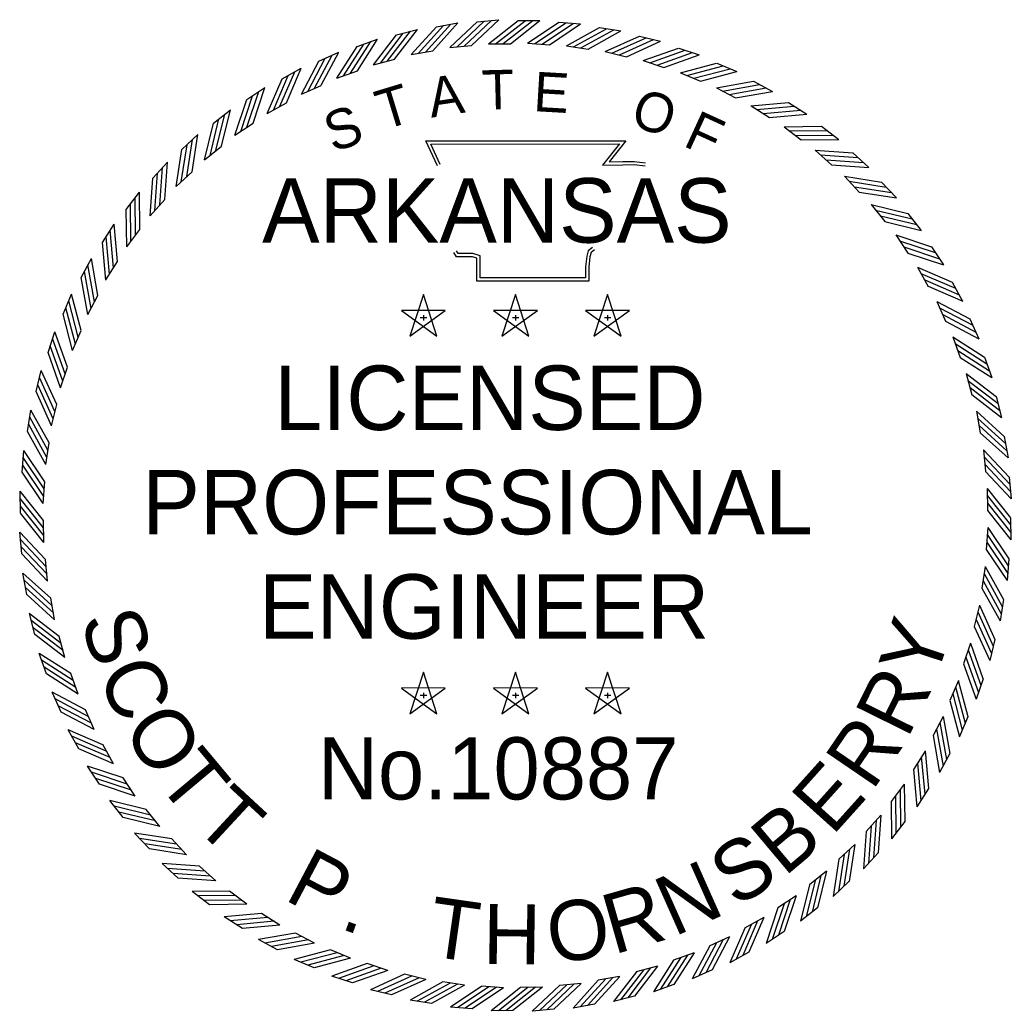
# Model space of a CAD drawing. Extents: x -31696 to 27919, y -8775 to 11152.
# Drawn here: x 3046.5 to 3294.9, y 323.2 to 571.6 of the extents above; entities that cross this region are included whole.
import ezdxf

# ---------------------------------------------------------------- set-up
doc = ezdxf.new("R2010")
doc.units = 0
doc.layers.add('Level 46', color=7, linetype='Continuous')

msp = doc.modelspace()

# ---------------------------------------------------------------- linework, layer by layer
at = {"layer": 'Level 46'}
for p, q in [((3161.08, 571.13), (3166.5, 571.63)), ((3171.39, 571.43), (3176.83, 571.43)), ((3140.85, 567.86), (3146.11, 569.24)), ((3150.9, 569.91), (3156.26, 570.86)), ((3181.58, 571.02), (3187, 570.63)), ((3191.75, 569.7), (3197.12, 568.86)), ((3131.01, 564.98), (3136.14, 566.8)), ((3201.77, 567.55), (3207.06, 566.26)), ((3154.22, 564.68), (3159.65, 565.18)), ((3163.96, 565.64), (3169.41, 565.64)), ((3173.75, 565.8), (3179.19, 565.4)), ((3183.51, 565.14), (3188.9, 564.29)), ((3211.59, 564.57), (3216.75, 562.85)), ((3121.43, 561.3), (3126.4, 563.53)), ((3135.14, 560.37), (3140.42, 561.76)), ((3144.59, 562.92), (3149.96, 563.87)), ((3193.19, 563.68), (3198.49, 562.39)), ((3112.2, 556.85), (3116.96, 559.48)), ((3202.71, 561.42), (3207.89, 559.7)), ((3221.12, 560.8), (3226.13, 558.66)), ((3125.94, 557.05), (3131.08, 558.87)), ((3212.02, 558.39), (3217.03, 556.25)), ((3103.36, 551.64), (3107.89, 554.66)), ((3117.04, 552.98), (3122.01, 555.21)), ((3221.04, 554.6), (3225.86, 552.05)), ((3230.31, 556.24), (3235.12, 553.7)), ((3094.98, 545.72), (3099.24, 549.11)), ((3108.5, 548.19), (3113.27, 550.83)), ((3229.72, 550.08), (3234.32, 547.14)), ((3239.1, 550.95), (3243.68, 548.02)), ((3100.39, 542.71), (3104.93, 545.73)), ((3238, 544.85), (3242.33, 541.54)), ((3247.41, 544.95), (3251.74, 541.64)), ((3087.12, 539.14), (3091.09, 542.86)), ((3092.76, 536.57), (3097.04, 539.96)), ((3245.82, 538.96), (3249.86, 535.3)), ((3255.21, 538.28), (3259.24, 534.63)), ((3079.83, 531.92), (3083.48, 535.96)), ((3085.67, 529.83), (3089.64, 533.56)), ((3253.12, 532.45), (3256.85, 528.47)), ((3262.42, 530.99), (3266.14, 527.02)), ((3073.17, 524.13), (3076.47, 528.45)), ((3079.15, 522.53), (3082.81, 526.58)), ((3259.86, 525.35), (3263.25, 521.08)), ((3269.01, 523.13), (3272.39, 518.87)), ((3067.16, 515.81), (3070.1, 520.39)), ((3073.26, 514.71), (3076.57, 519.05)), ((3265.99, 517.72), (3269.02, 513.18)), ((3274.93, 514.75), (3277.94, 510.23)), ((3061.87, 507.03), (3064.41, 511.84)), ((3068.04, 506.44), (3070.98, 511.03)), ((3271.47, 509.61), (3274.11, 504.84)), ((3280.13, 505.92), (3282.76, 501.15)), ((3057.32, 497.84), (3059.46, 502.84)), ((3063.51, 497.76), (3066.06, 502.58)), ((3147.61, 502.79), (3144.21, 492.34)), ((3151, 492.35), (3147.62, 502.8)), ((3170.69, 502.79), (3167.28, 492.34)), ((3174.08, 492.35), (3170.7, 502.8)), ((3193.77, 502.79), (3190.36, 492.34)), ((3197.16, 492.35), (3193.77, 502.8)), ((3276.26, 501.08), (3278.5, 496.1)), ((3153.1, 498.8), (3142.11, 498.81)), ((3142.12, 498.8), (3151, 492.33)), ((3144.22, 492.35), (3153.11, 498.8)), ((3146.83, 497.04), (3148.46, 497.04)), ((3147.62, 497.63), (3147.62, 496.25)), ((3176.18, 498.8), (3165.19, 498.81)), ((3165.2, 498.8), (3174.08, 492.33)), ((3167.3, 492.35), (3176.19, 498.8)), ((3169.91, 497.04), (3171.54, 497.04)), ((3170.7, 497.63), (3170.7, 496.25)), ((3199.25, 498.8), (3188.27, 498.81)), ((3188.28, 498.8), (3197.16, 492.33)), ((3190.37, 492.35), (3199.27, 498.8)), ((3192.98, 497.04), (3194.62, 497.04)), ((3193.78, 497.63), (3193.78, 496.25)), ((3284.59, 496.68), (3286.82, 491.72)), ((3053.54, 488.3), (3055.26, 493.47)), ((3059.72, 488.74), (3061.86, 493.75)), ((3280.33, 492.18), (3282.15, 487.03)), ((3288.27, 487.11), (3290.08, 481.98)), ((3056.69, 479.43), (3058.41, 484.6)), ((3050.56, 478.49), (3051.85, 483.78)), ((3283.66, 482.97), (3285.04, 477.69)), ((3291.14, 477.26), (3292.53, 472)), ((3054.43, 469.91), (3055.72, 475.2)), ((3048.41, 468.46), (3049.25, 473.84)), ((3286.21, 473.52), (3287.15, 468.15)), ((3293.2, 467.21), (3294.14, 461.86)), ((3052.97, 460.23), (3053.82, 465.61)), ((3047.09, 458.29), (3047.49, 463.72)), ((3287.97, 463.89), (3288.47, 458.46)), ((3052.32, 450.46), (3052.72, 455.9)), ((3294.41, 457.03), (3294.91, 451.61)), ((3046.61, 448.05), (3046.56, 453.49)), ((3288.93, 454.15), (3288.98, 448.7)), ((3052.47, 440.68), (3052.42, 446.13)), ((3294.79, 446.78), (3294.84, 441.34)), ((3046.98, 437.8), (3046.48, 443.22)), ((3289.08, 444.37), (3288.68, 438.93)), ((3053.43, 430.94), (3052.93, 436.37)), ((3294.31, 436.54), (3293.91, 431.11)), ((3048.2, 427.61), (3047.25, 432.97)), ((3288.42, 434.6), (3287.58, 429.21)), ((3055.19, 421.31), (3054.24, 426.68)), ((3286.96, 424.92), (3285.67, 419.62)), ((3292.99, 426.36), (3292.14, 420.99)), ((3050.25, 417.57), (3048.87, 422.83)), ((3057.74, 411.86), (3056.35, 417.13)), ((3284.71, 415.4), (3282.99, 410.22)), ((3290.83, 416.34), (3289.55, 411.05)), ((3053.13, 407.72), (3051.32, 412.85)), ((3061.06, 402.65), (3059.24, 407.79)), ((3147.61, 408.16), (3144.21, 397.72)), ((3151, 397.72), (3147.62, 408.17)), ((3170.69, 408.16), (3167.28, 397.72)), ((3174.08, 397.72), (3170.7, 408.17)), ((3193.77, 408.16), (3190.36, 397.72)), ((3197.16, 397.72), (3193.77, 408.17)), ((3281.68, 406.09), (3279.53, 401.08)), ((3287.86, 406.52), (3286.14, 401.36)), ((3056.81, 398.15), (3054.58, 403.11)), ((3153.1, 404.17), (3142.11, 404.19)), ((3142.12, 404.17), (3151, 397.71)), ((3144.22, 397.72), (3153.11, 404.17)), ((3147.62, 403.01), (3147.62, 401.63)), ((3176.18, 404.17), (3165.19, 404.19)), ((3165.2, 404.17), (3174.08, 397.71)), ((3167.3, 397.72), (3176.19, 404.17)), ((3170.7, 403.01), (3170.7, 401.63)), ((3199.25, 404.17), (3188.27, 404.19)), ((3188.28, 404.17), (3197.16, 397.71)), ((3190.37, 397.72), (3199.27, 404.17)), ((3193.78, 403.01), (3193.78, 401.63)), ((3146.83, 402.42), (3148.46, 402.42)), ((3169.91, 402.42), (3171.54, 402.42)), ((3192.98, 402.42), (3194.62, 402.42)), ((3065.13, 393.75), (3062.9, 398.72)), ((3277.89, 397.07), (3275.33, 392.25)), ((3284.08, 396.99), (3281.94, 391.99)), ((3061.27, 388.91), (3058.63, 393.67)), ((3069.93, 385.22), (3067.29, 389.99)), ((3273.36, 388.39), (3270.42, 383.8)), ((3279.53, 387.8), (3276.98, 382.99)), ((3066.47, 380.07), (3063.45, 384.6)), ((3075.41, 377.11), (3072.38, 381.65)), ((3268.14, 380.11), (3264.83, 375.78)), ((3274.23, 379.01), (3271.3, 374.43)), ((3072.39, 371.7), (3069.01, 375.96)), ((3081.54, 369.48), (3078.15, 373.75)), ((3262.25, 372.3), (3258.59, 368.25)), ((3268.23, 370.7), (3264.93, 366.37)), ((3078.98, 363.84), (3075.25, 367.81)), ((3088.28, 362.38), (3084.55, 366.36)), ((3255.73, 364.99), (3251.75, 361.26)), ((3261.56, 362.91), (3257.92, 358.87)), ((3086.19, 356.55), (3082.15, 360.2)), ((3095.58, 355.87), (3091.54, 359.52)), ((3248.63, 358.25), (3244.36, 354.86)), ((3254.27, 355.69), (3250.31, 351.97)), ((3093.98, 349.88), (3089.66, 353.18)), ((3103.4, 349.98), (3099.06, 353.29)), ((3241, 352.12), (3236.47, 349.1)), ((3246.41, 349.1), (3242.15, 345.72)), ((3102.3, 343.88), (3097.72, 346.81)), ((3111.67, 344.75), (3107.08, 347.69)), ((3232.9, 346.64), (3228.12, 344)), ((3238.04, 343.19), (3233.51, 340.17)), ((3111.08, 338.58), (3106.27, 341.13)), ((3120.35, 340.23), (3115.53, 342.78)), ((3224.36, 341.85), (3219.39, 339.61)), ((3129.38, 336.44), (3124.36, 338.58)), ((3229.2, 337.98), (3224.44, 335.35)), ((3120.27, 334.03), (3115.27, 336.17)), ((3215.46, 337.78), (3210.32, 335.96)), ((3138.68, 333.4), (3133.51, 335.13)), ((3206.25, 334.46), (3200.98, 333.07)), ((3219.96, 333.52), (3215, 331.29)), ((3129.81, 330.26), (3124.65, 331.97)), ((3148.21, 331.15), (3142.91, 332.44)), ((3157.88, 329.69), (3152.5, 330.54)), ((3196.8, 331.91), (3191.43, 330.96)), ((3139.62, 327.28), (3134.34, 328.57)), ((3167.65, 329.03), (3162.21, 329.43)), ((3177.44, 329.18), (3171.98, 329.13)), ((3187.18, 330.14), (3181.75, 329.64)), ((3210.39, 329.84), (3205.26, 328.03)), ((3149.65, 325.12), (3144.28, 325.97)), ((3200.55, 326.97), (3195.28, 325.58)), ((3159.82, 323.8), (3154.39, 324.2)), ((3170.07, 323.33), (3164.62, 323.28)), ((3180.31, 323.7), (3174.9, 323.2)), ((3190.5, 324.91), (3185.14, 323.97))]:
    msp.add_line(p, q, dxfattribs=at)
for points in [[(3157.84, 565.04), (3164.7, 571.48)], [(3159.64, 565.19), (3166.5, 571.63)], [(3163.95, 565.64), (3171.38, 571.43)], [(3165.71, 565.62), (3173.13, 571.41)], [(3167.6, 565.66), (3175.02, 571.45)], [(3169.41, 565.65), (3176.83, 571.44)], [(3140.41, 561.76), (3146.12, 569.25)], [(3144.59, 562.92), (3150.89, 569.91)], [(3146.31, 563.2), (3152.62, 570.19)], [(3148.17, 563.57), (3154.47, 570.56)], [(3149.96, 563.87), (3156.26, 570.86)], [(3154.21, 564.68), (3161.08, 571.12)], [(3155.96, 564.82), (3162.82, 571.27)], [(3173.74, 565.79), (3181.57, 571.02)], [(3175.49, 565.65), (3183.31, 570.88)], [(3177.37, 565.55), (3185.2, 570.78)], [(3179.18, 565.4), (3187.01, 570.63)], [(3183.51, 565.14), (3191.74, 569.7)], [(3185.23, 564.85), (3193.47, 569.41)], [(3187.11, 564.59), (3195.34, 569.16)], [(3131.07, 558.87), (3136.14, 566.8)], [(3135.14, 560.36), (3140.84, 567.85)], [(3136.84, 560.79), (3142.54, 568.28)], [(3138.65, 561.32), (3144.36, 568.8)], [(3188.89, 564.3), (3197.13, 568.86)], [(3193.18, 563.68), (3201.77, 567.55)], [(3194.88, 563.25), (3203.46, 567.12)], [(3196.73, 562.84), (3205.31, 566.71)], [(3125.93, 557.04), (3131, 564.98)], [(3127.59, 557.61), (3132.66, 565.54)], [(3129.36, 558.28), (3134.42, 566.21)], [(3198.48, 562.39), (3207.07, 566.26)], [(3202.71, 561.42), (3211.58, 564.57)], [(3204.36, 560.85), (3213.24, 564)], [(3118.64, 553.67), (3123.03, 562)], [(3120.34, 554.49), (3124.74, 562.81)], [(3122, 555.22), (3126.4, 563.54)], [(3206.17, 560.3), (3215.04, 563.44)], [(3207.88, 559.71), (3216.76, 562.85)], [(3113.27, 550.83), (3116.96, 559.49)], [(3117.03, 552.97), (3121.43, 561.3)], [(3212.01, 558.39), (3221.11, 560.79)], [(3213.62, 557.69), (3222.72, 560.09)], [(3215.37, 556.98), (3224.47, 559.39)], [(3108.5, 548.18), (3112.19, 556.84)], [(3110.04, 549.01), (3113.73, 557.67)], [(3111.67, 549.96), (3115.37, 558.62)], [(3217.03, 556.25), (3226.13, 558.66)], [(3104.92, 545.73), (3107.89, 554.67)], [(3221.04, 554.6), (3230.31, 556.24)], [(3222.58, 553.77), (3231.85, 555.41)], [(3224.27, 552.92), (3233.54, 554.56)], [(3100.39, 542.7), (3103.36, 551.63)], [(3101.86, 543.66), (3104.82, 552.59)], [(3103.41, 544.74), (3106.37, 553.67)], [(3225.86, 552.06), (3235.13, 553.7)], [(3097.03, 539.96), (3099.25, 549.11)], [(3229.71, 550.08), (3239.09, 550.95)], [(3231.18, 549.12), (3240.55, 549.99)], [(3094.14, 537.64), (3096.36, 546.79)], [(3095.6, 538.85), (3097.82, 548)], [(3232.8, 548.13), (3242.17, 549.01)], [(3234.31, 547.14), (3243.69, 548.02)], [(3092.76, 536.57), (3094.98, 545.72)], [(3237.99, 544.85), (3247.4, 544.95)], [(3088.3, 532.34), (3089.76, 541.64)], [(3089.64, 533.56), (3091.09, 542.86)], [(3239.37, 543.78), (3248.79, 543.87)], [(3240.9, 542.66), (3250.31, 542.76)], [(3242.33, 541.55), (3251.74, 541.64)], [(3085.67, 529.83), (3087.12, 539.13)], [(3086.95, 531.01), (3088.41, 540.31)], [(3151.11, 535.02), (3148.21, 541.3), (3198.39, 541.33), (3194.2, 536.06), (3197.61, 536.11), (3200.46, 536.14), (3203.3, 535.83)], [(3151.84, 535.35), (3149.46, 540.5), (3196.74, 540.53), (3192.54, 535.24), (3197.62, 535.31), (3200.42, 535.35), (3203.22, 535.04)], [(3245.81, 538.96), (3255.2, 538.28)], [(3247.1, 537.78), (3256.49, 537.09)], [(3081.57, 525.24), (3082.25, 534.63)], [(3082.8, 526.57), (3083.48, 535.96)], [(3248.53, 536.54), (3257.92, 535.86)], [(3249.86, 535.31), (3259.25, 534.63)], [(3079.15, 522.52), (3079.83, 531.91)], [(3080.34, 523.81), (3081.02, 533.2)], [(3253.11, 532.45), (3262.41, 530.99)], [(3254.3, 531.16), (3263.6, 529.7)], [(3255.62, 529.81), (3264.92, 528.35)], [(3075.45, 517.62), (3075.35, 527.03)], [(3076.56, 519.05), (3076.47, 528.46)], [(3256.85, 528.47), (3266.15, 527.02)], [(3074.34, 516.09), (3074.24, 525.5)], [(3259.85, 525.35), (3269, 523.13)], [(3073.26, 514.71), (3073.16, 524.12)], [(3260.93, 523.97), (3270.08, 521.75)], [(3262.13, 522.51), (3271.28, 520.3)], [(3070.97, 511.03), (3070.1, 520.4)], [(3263.25, 521.08), (3272.4, 518.87)], [(3068.99, 507.9), (3068.12, 517.27)], [(3069.98, 509.51), (3069.1, 518.88)], [(3265.98, 517.72), (3274.92, 514.76)], [(3068.04, 506.43), (3067.16, 515.8)], [(3189.98, 514.61), (3188.93, 513.75), (3188.56, 512.4), (3188.27, 509.7), (3188.27, 506.98), (3161.85, 506.98), (3161.85, 510.87), (3161.85, 512.49), (3160.03, 513.05), (3156.36, 513.05), (3155.89, 513.77)], [(3266.94, 516.26), (3275.88, 513.29)], [(3268.02, 514.71), (3276.96, 511.74)], [(3066.06, 502.57), (3064.41, 511.84)], [(3190.49, 513.99), (3189.63, 513.29), (3189.35, 512.25), (3189.06, 509.65), (3189.06, 506.18), (3161.05, 506.18), (3161.05, 510.87), (3161.05, 511.91), (3159.91, 512.25), (3155.93, 512.25), (3155.22, 513.33)], [(3269.02, 513.19), (3277.95, 510.22)], [(3065.19, 500.98), (3063.55, 510.25)], [(3271.46, 509.61), (3280.12, 505.92)], [(3063.51, 497.75), (3061.87, 507.02)], [(3064.35, 499.29), (3062.7, 508.56)], [(3272.3, 508.07), (3280.96, 504.38)], [(3273.25, 506.44), (3281.91, 502.75)], [(3274.11, 504.85), (3282.77, 501.15)], [(3061.86, 493.75), (3059.46, 502.85)], [(3060.43, 490.33), (3058.02, 499.43)], [(3061.13, 492.09), (3058.73, 501.19)], [(3276.26, 501.08), (3284.58, 496.68)], [(3276.96, 499.48), (3285.28, 495.08)], [(3059.72, 488.73), (3057.32, 497.83)], [(3277.77, 497.77), (3286.1, 493.37)], [(3278.5, 496.11), (3286.83, 491.71)], [(3058.4, 484.6), (3055.26, 493.47)], [(3280.33, 492.18), (3288.26, 487.11)], [(3057.26, 481.08), (3054.11, 489.95)], [(3057.82, 482.88), (3054.67, 491.76)], [(3280.9, 490.52), (3288.83, 485.46)], [(3056.69, 479.42), (3053.54, 488.29)], [(3281.57, 488.76), (3289.5, 483.69)], [(3282.15, 487.04), (3290.09, 481.97)], [(3055.27, 473.44), (3051.4, 482.02)], [(3055.72, 475.2), (3051.85, 483.78)], [(3283.65, 482.97), (3291.14, 477.27)], [(3054.87, 471.6), (3051, 480.18)], [(3284.08, 481.28), (3291.57, 475.57)], [(3054.44, 469.9), (3050.57, 478.48)], [(3284.6, 479.46), (3292.09, 473.75)], [(3285.05, 477.7), (3292.53, 472)], [(3053.52, 463.82), (3048.95, 472.05)], [(3053.82, 465.61), (3049.25, 473.84)], [(3286.2, 473.53), (3293.19, 467.22)], [(3053.26, 461.95), (3048.7, 470.18)], [(3286.49, 471.8), (3293.48, 465.49)], [(3286.86, 469.94), (3293.85, 463.64)], [(3052.98, 460.22), (3048.41, 468.45)], [(3287.16, 468.16), (3294.15, 461.85)], [(3052.71, 455.89), (3047.48, 463.72)], [(3287.96, 463.9), (3294.41, 457.04)], [(3288.11, 462.15), (3294.55, 455.29)], [(3052.47, 452.2), (3047.24, 460.03)], [(3052.56, 454.09), (3047.33, 461.92)], [(3288.32, 460.27), (3294.77, 453.41)], [(3052.32, 450.46), (3047.09, 458.28)], [(3288.47, 458.47), (3294.92, 451.61)], [(3052.41, 446.12), (3046.56, 453.49)], [(3288.92, 454.16), (3294.78, 446.79)], [(3288.92, 452.41), (3294.78, 445.04)], [(3052.41, 444.31), (3046.56, 451.68)], [(3052.47, 442.42), (3046.62, 449.79)], [(3288.98, 450.52), (3294.84, 443.15)], [(3052.47, 440.67), (3046.62, 448.04)], [(3288.98, 448.7), (3294.84, 441.33)], [(3052.93, 436.36), (3046.48, 443.22)], [(3288.93, 442.63), (3294.16, 434.8)], [(3289.08, 444.37), (3294.31, 436.54)], [(3053.08, 434.55), (3046.63, 441.41)], [(3288.83, 440.74), (3294.06, 432.91)], [(3053.29, 432.67), (3046.84, 439.54)], [(3053.43, 430.93), (3046.99, 437.79)], [(3288.68, 438.93), (3293.91, 431.1)], [(3054.24, 426.67), (3047.25, 432.98)], [(3288.13, 432.88), (3292.7, 424.65)], [(3288.42, 434.61), (3292.99, 426.37)], [(3054.54, 424.88), (3047.55, 431.19)], [(3287.88, 431.01), (3292.44, 422.77)], [(3054.91, 423.03), (3047.92, 429.33)], [(3055.2, 421.3), (3048.21, 427.61)], [(3287.58, 429.22), (3292.15, 420.98)], [(3286.96, 424.93), (3290.83, 416.35)], [(3056.35, 417.13), (3048.86, 422.83)], [(3286.53, 423.23), (3290.4, 414.65)], [(3056.8, 415.37), (3049.31, 421.07)], [(3286.12, 421.39), (3289.99, 412.8)], [(3057.32, 413.55), (3049.83, 419.26)], [(3057.75, 411.85), (3050.26, 417.56)], [(3285.68, 419.63), (3289.55, 411.05)], [(3284.71, 415.41), (3287.85, 406.53)], [(3059.24, 407.79), (3051.31, 412.85)], [(3284.14, 413.75), (3287.29, 404.88)], [(3059.83, 406.07), (3051.9, 411.14)], [(3282.99, 410.23), (3286.14, 401.36)], [(3283.58, 411.94), (3286.73, 403.07)], [(3060.5, 404.3), (3052.57, 409.37)], [(3061.07, 402.65), (3053.14, 407.72)], [(3281.67, 406.1), (3284.08, 397)], [(3062.9, 398.72), (3054.57, 403.11)], [(3280.27, 402.74), (3282.67, 393.64)], [(3280.97, 404.5), (3283.37, 395.39)], [(3063.62, 397.06), (3055.3, 401.45)], [(3279.54, 401.08), (3281.94, 391.98)], [(3064.44, 395.35), (3056.11, 399.75)], [(3065.14, 393.75), (3056.82, 398.14)], [(3277.05, 395.54), (3278.69, 386.27)], [(3277.88, 397.08), (3279.53, 387.81)], [(3067.29, 389.98), (3058.63, 393.67)], [(3276.2, 393.85), (3277.85, 384.58)], [(3068.15, 388.39), (3059.49, 392.08)], [(3069.1, 386.75), (3060.44, 390.45)], [(3275.34, 392.25), (3276.98, 382.98)], [(3069.93, 385.21), (3061.27, 388.91)], [(3273.36, 388.4), (3274.23, 379.02)], [(3271.42, 385.32), (3272.29, 375.94)], [(3272.4, 386.93), (3273.28, 377.56)], [(3072.38, 381.64), (3063.45, 384.6)], [(3073.37, 380.12), (3064.44, 383.09)], [(3270.43, 383.8), (3271.3, 374.43)], [(3074.46, 378.57), (3065.52, 381.54)], [(3268.14, 380.12), (3268.23, 370.71)], [(3075.41, 377.1), (3066.48, 380.07)], [(3267.06, 378.74), (3267.16, 369.33)], [(3078.15, 373.74), (3069, 375.96)], [(3264.83, 375.78), (3264.93, 366.37)], [(3265.95, 377.21), (3266.04, 367.8)], [(3079.26, 372.31), (3070.11, 374.53)], [(3080.47, 370.86), (3071.32, 373.08)], [(3081.55, 369.48), (3072.4, 371.69)], [(3261.06, 371.02), (3260.38, 361.63)], [(3262.25, 372.3), (3261.57, 362.91)], [(3084.55, 366.35), (3075.25, 367.81)], [(3258.6, 368.25), (3257.92, 358.86)], [(3259.82, 369.59), (3259.14, 360.2)], [(3085.78, 365.02), (3076.48, 366.47)], [(3087.1, 363.67), (3077.8, 365.12)], [(3088.29, 362.38), (3078.98, 363.84)], [(3254.44, 363.81), (3252.99, 354.51)], [(3255.73, 365), (3254.28, 355.7)], [(3251.76, 361.26), (3250.3, 351.96)], [(3253.09, 362.49), (3251.64, 353.19)], [(3091.54, 359.52), (3082.15, 360.2)], [(3092.87, 358.29), (3083.48, 358.97)], [(3248.64, 358.26), (3246.42, 349.11)], [(3094.3, 357.05), (3084.91, 357.73)], [(3095.59, 355.87), (3086.2, 356.55)], [(3245.8, 355.98), (3243.58, 346.83)], [(3247.25, 357.18), (3245.04, 348.04)], [(3099.07, 353.28), (3089.65, 353.18)], [(3244.37, 354.86), (3242.15, 345.72)], [(3100.5, 352.16), (3091.08, 352.07)], [(3102.02, 351.05), (3092.61, 350.96)], [(3239.54, 351.17), (3236.58, 342.24)], [(3241.01, 352.13), (3238.04, 343.19)], [(3103.41, 349.98), (3093.99, 349.88)], [(3236.47, 349.1), (3233.51, 340.16)], [(3237.99, 350.09), (3235.03, 341.15)], [(3107.08, 347.68), (3097.71, 346.81)], [(3108.6, 346.69), (3099.23, 345.82)], [(3110.22, 345.71), (3100.84, 344.84)], [(3231.36, 345.81), (3227.66, 337.16)], [(3232.9, 346.65), (3229.2, 337.99)], [(3111.68, 344.75), (3102.31, 343.88)], [(3228.13, 344), (3224.44, 335.34)], [(3229.72, 344.86), (3226.03, 336.2)], [(3115.54, 342.77), (3106.27, 341.13)], [(3117.13, 341.91), (3107.86, 340.27)], [(3118.82, 341.06), (3109.55, 339.42)], [(3222.76, 341.15), (3218.37, 332.83)], [(3224.36, 341.86), (3219.97, 333.53)], [(3120.36, 340.23), (3111.09, 338.58)], [(3124.37, 338.57), (3115.26, 336.17)], [(3219.39, 339.61), (3215, 331.29)], [(3221.05, 340.34), (3216.66, 332.01)], [(3126.03, 337.85), (3116.92, 335.44)], [(3127.78, 337.14), (3118.68, 334.74)], [(3129.38, 336.44), (3120.28, 334.03)], [(3210.33, 335.96), (3205.26, 328.02)], [(3212.04, 336.55), (3206.97, 328.61)], [(3213.81, 337.22), (3208.74, 329.28)], [(3215.46, 337.78), (3210.4, 329.85)], [(3133.51, 335.12), (3124.64, 331.97)], [(3135.23, 334.53), (3126.35, 331.38)], [(3137.03, 333.97), (3128.16, 330.83)], [(3138.69, 333.41), (3129.82, 330.26)], [(3200.99, 333.07), (3195.28, 325.58)], [(3202.74, 333.51), (3197.04, 326.02)], [(3204.56, 334.03), (3198.85, 326.54)], [(3206.26, 334.46), (3200.55, 326.97)], [(3142.91, 332.43), (3134.33, 328.56)], [(3144.67, 331.99), (3136.09, 328.12)], [(3146.52, 331.58), (3137.93, 327.71)], [(3148.21, 331.15), (3139.63, 327.28)], [(3152.5, 330.53), (3144.27, 325.97)], [(3191.44, 330.96), (3185.14, 323.96)], [(3193.23, 331.25), (3186.92, 324.26)], [(3195.08, 331.62), (3188.78, 324.63)], [(3196.81, 331.91), (3190.5, 324.92)], [(3154.29, 330.23), (3146.06, 325.67)], [(3156.16, 329.98), (3147.93, 325.42)], [(3157.89, 329.69), (3149.66, 325.13)], [(3162.22, 329.43), (3154.39, 324.2)], [(3164.02, 329.28), (3156.2, 324.05)], [(3165.91, 329.18), (3158.08, 323.95)], [(3167.66, 329.04), (3159.83, 323.81)], [(3171.99, 329.13), (3164.62, 323.27)], [(3173.8, 329.13), (3166.43, 323.27)], [(3175.69, 329.19), (3168.32, 323.33)], [(3177.44, 329.19), (3170.07, 323.33)], [(3181.75, 329.64), (3174.89, 323.19)], [(3183.56, 329.79), (3176.7, 323.34)], [(3185.44, 330.01), (3178.58, 323.56)], [(3187.18, 330.15), (3180.32, 323.7)]]:
    msp.add_lwpolyline(points, dxfattribs=at)

# ---------------------------------------------------------------- texts
for s, height, rotation, p in [('T', 9.9, 1.4789, (3162.37, 549.07)), ('A', 9.9, 8.6788, (3149.58, 547.1)), ('E', 9.9, 356.672, (3175.03, 548.77)), ('T', 9.9, 16.9015, (3137.57, 543.96)), ('O', 9.9, 341.2218, (3199.07, 545.37)), ('S', 9.9, 19.7726, (3124.98, 538.31)), ('F', 9.9, 335.3628, (3212.41, 540.16)), ('S', 15.03, 286.9475, (3061.59, 421.47)), ('Y', 15.03, 71.7733, (3275.78, 405.43)), ('C', 15.03, 294.2435, (3065.77, 407.76)), ('R', 15.03, 63.7477, (3268.9, 391.25)), ('O', 15.03, 301.9044, (3071.99, 394.05)), ('R', 15.03, 55.7221, (3260.1, 378.16)), ('T', 15.03, 309.93, (3080.41, 380.72)), ('E', 15.03, 48.0613, (3250.08, 366.93)), ('T', 15.03, 317.226, (3089.62, 369.73)), ('B', 15.03, 40.0357, (3238.07, 356.71)), ('S', 15.03, 32.7397, (3226.01, 348.95)), ('P', 15.03, 332.1828, (3112.43, 351.3)), ('N', 15.03, 23.9845, (3210.39, 341.76)), ('R', 15.03, 15.9589, (3195.26, 337.33)), ('T', 15.03, 351.882, (3148.26, 337.1)), ('O', 15.03, 7.9332, (3179.65, 335.05)), ('H', 15.03, 359.178, (3162.46, 335.08)), ('.', 15.03, 340.2084, (3126.42, 344.03))]:
    msp.add_text(s, height=height, rotation=rotation, dxfattribs=at).set_placement(p)
for s, height, p in [('ARKANSAS', 16.155, (3107.2, 515.79)), ('LICENSED', 16.155, (3110.27, 468.84)), ('PROFESSIONAL', 16.1547, (3077.19, 442.69)), ('ENGINEER', 16.155, (3106.43, 416.53)), ('No.10887', 15.578, (3121.19, 376.25))]:
    msp.add_text(s, height=height, dxfattribs=at).set_placement(p)

doc.saveas('drawing.dxf')
